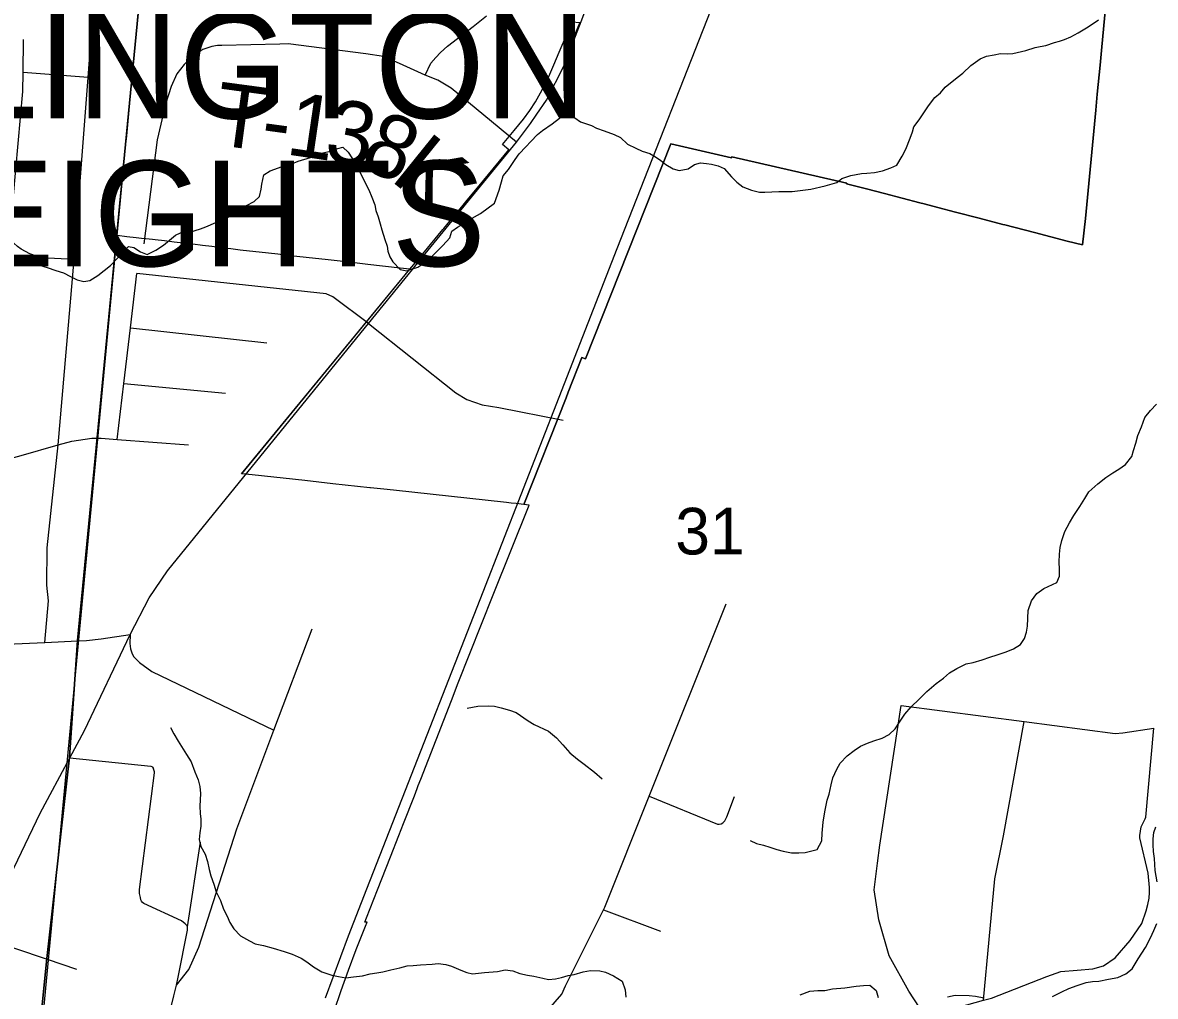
# Model space of a CAD drawing. Extents: x 0 to 34, y -3.9 to 26.2.
# Drawn here: x 2.843 to 3.859, y 17.395 to 18.269 of the extents above; entities that cross this region are included whole.
import ezdxf

# ---------------------------------------------------------------- set-up
doc = ezdxf.new("R2010")
doc.units = 0
for name, color, linetype in [('GM_X_City_Street', 7, 'Continuous'), ('GM_X_Corporation', 7, 'Continuous'), ('GM_X_Corporation_Text', 7, 'Continuous'), ('GM_X_County_Road', 7, 'Continuous'), ('GM_X_Interchange_Ramps', 7, 'Continuous'), ('GM_X_Interstate_Route', 7, 'Continuous'), ('GM_X_Minor_River', 7, 'Continuous'), ('GM_X_Rail_Line', 7, 'Continuous'), ('GM_X_Section', 7, 'Continuous'), ('GM_X_Section_Text', 7, 'Continuous'), ('GM_X_State_Shield', 7, 'Continuous'), ('GM_X_Township_Road', 7, 'Continuous'), ('GM_X_Township_Road_Text', 7, 'Continuous'), ('GM_X_US_Route', 7, 'Continuous')]:
    doc.layers.add(name, color=color, linetype=linetype)

msp = doc.modelspace()

# ---------------------------------------------------------------- linework, layer by layer
at = {"layer": 'GM_X_City_Street'}
for p, q in [((2.9019, 18.2193), (2.8434, 18.2239)), ((2.9397, 17.9947), (3.0621, 17.9811)), ((2.9338, 17.9448), (3.0249, 17.9362)), ((2.9901, 17.6713), (3.0685, 17.6337)), ((2.991, 17.457), (3.0027, 17.533)), ((3.3641, 17.4723), (3.4151, 17.4532))]:
    msp.add_line(p, q, dxfattribs=at)
for points in [[(2.8893, 18.056), (2.8601, 18.0575), (2.8563, 18.0587), (2.8495, 18.0612), (2.8416, 18.0654), (2.8383, 18.0676), (2.8351, 18.0708), (2.8336, 18.0729), (2.8328, 18.0749), (2.8323, 18.0804), (2.8328, 18.0901), (2.8433, 18.2068), (2.8434, 18.2239), (2.8437, 18.2535)], [(2.8629, 17.7123), (2.8661, 17.7496), (2.8646, 17.7637), (2.865, 17.7972), (2.8748, 17.8896), (2.8893, 18.056), (2.9019, 18.2193), (2.9049, 18.2592)], [(2.9278, 17.8946), (2.9338, 17.9448), (2.9397, 17.9947), (2.9455, 18.0435)], [(3.1534, 17.9985), (3.1212, 18.0225), (3.1152, 18.0253), (2.9455, 18.0435)], [(3.1534, 17.9985), (3.2317, 17.9364), (3.2415, 17.9304), (3.2554, 17.9255), (3.2701, 17.9232), (3.3278, 17.9118)], [(2.6306, 17.8842), (2.6867, 17.8819), (2.6993, 17.8814), (2.8142, 17.8768), (2.815, 17.8767), (2.8298, 17.8767), (2.8416, 17.8802), (2.8748, 17.8896), (2.8871, 17.8931), (2.905, 17.8956), (2.9102, 17.8957), (2.9134, 17.8958), (2.9278, 17.8946), (2.9919, 17.8896)], [(3.2531, 17.0012), (3.2564, 17.0369), (3.2762, 17.2484), (3.2789, 17.2779), (3.2811, 17.3213), (3.282, 17.3401), (3.2822, 17.3432), (3.2833, 17.3458), (3.2862, 17.3499), (3.2928, 17.3577), (3.3268, 17.3967), (3.3301, 17.4042), (3.3641, 17.4723), (3.3652, 17.4746), (3.4052, 17.5744), (3.4742, 17.7469)], [(2.981, 17.4048), (2.992, 17.4189), (3.0011, 17.4389), (3.0353, 17.545), (3.0685, 17.6337), (3.1027, 17.7247)], [(2.9396, 17.7194), (2.9392, 17.7114), (2.9399, 17.7065), (2.9412, 17.7021), (2.9429, 17.6994), (2.9479, 17.6942), (2.9588, 17.6864), (2.9901, 17.6713)], [(3.6576, 17.3692), (3.6379, 17.3994), (3.6205, 17.431), (3.6111, 17.4635), (3.6068, 17.4902), (3.61, 17.5142), (3.612, 17.5303), (3.6312, 17.6558)], [(3.6312, 17.6558), (3.7416, 17.6413), (3.8232, 17.6305), (3.83, 17.6311), (3.8578, 17.6353)], [(3.705, 17.3912), (3.7152, 17.5002), (3.723, 17.5387), (3.7416, 17.6413)], [(3.823, 17.4293), (3.8367, 17.4449), (3.8469, 17.4602), (3.851, 17.4715), (3.8524, 17.4771), (3.8535, 17.4828), (3.8538, 17.4878), (3.8538, 17.4923), (3.8526, 17.5052), (3.8451, 17.5369), (3.8453, 17.5392), (3.8465, 17.5468), (3.8501, 17.554), (3.8505, 17.5554), (3.8578, 17.6353)], [(2.8854, 17.6088), (2.9581, 17.6014), (2.959, 17.6009), (2.9596, 17.6004), (2.9604, 17.599)], [(2.991, 17.457), (2.9903, 17.4584), (2.9889, 17.4597), (2.9855, 17.4624), (2.9517, 17.4781), (2.9506, 17.4789), (2.9498, 17.48), (2.9492, 17.4813), (2.9488, 17.4835), (2.948, 17.4871), (2.9478, 17.4907), (2.9613, 17.5953), (2.9612, 17.5962), (2.9604, 17.599)], [(3.4052, 17.5744), (3.4663, 17.5493), (3.4678, 17.5491), (3.4698, 17.5495), (3.4711, 17.5504), (3.473, 17.5523), (3.4746, 17.5559), (3.4815, 17.574)], [(2.981, 17.4048), (2.9827, 17.412), (2.9908, 17.454), (2.9908, 17.4553), (2.991, 17.457)], [(2.8053, 17.4482), (2.865, 17.4281), (2.8913, 17.4192)], [(3.6576, 17.3692), (3.6647, 17.3778), (3.6704, 17.3818), (3.6827, 17.3849), (3.705, 17.3912), (3.7121, 17.3932), (3.7619, 17.4124), (3.7745, 17.417), (3.7889, 17.4181), (3.803, 17.4193), (3.8126, 17.422), (3.823, 17.4293)], [(2.9695, 17.3546), (2.9732, 17.3738), (2.9742, 17.3765), (2.9787, 17.3951), (2.981, 17.4048)]]:
    msp.add_lwpolyline(points, dxfattribs=at)
at = {"layer": 'GM_X_Corporation'}
for points in [[(3.8147, 18.2851), (3.8108, 18.2437), (3.8096, 18.2306), (3.8071, 18.2043), (3.8057, 18.1902), (3.7965, 18.0928), (3.7938, 18.0691), (3.7801, 18.0726), (3.7508, 18.0802), (3.724, 18.0872), (3.7224, 18.0876), (3.7011, 18.0931), (3.6799, 18.0986), (3.6639, 18.1028), (3.6518, 18.1059), (3.648, 18.107), (3.632, 18.1111), (3.6161, 18.1153), (3.6001, 18.1194), (3.5821, 18.1239), (3.5824, 18.1247), (3.4791, 18.1481), (3.479, 18.1473), (3.4246, 18.16), (3.348, 17.9668), (3.3448, 17.968), (3.3325, 17.9371), (3.3305, 17.932), (3.2926, 17.8361), (3.2859, 17.8369), (3.2812, 17.8374), (3.2791, 17.8376), (3.2771, 17.8378), (3.1756, 17.8489), (3.1672, 17.8498), (3.1551, 17.8511), (3.1546, 17.8512), (3.1213, 17.8548), (3.0963, 17.8576), (3.0488, 17.8628), (3.0395, 17.8637), (3.1905, 18.0475), (3.1974, 18.0555), (3.1991, 18.0576), (3.202, 18.0612), (3.2201, 18.083), (3.2204, 18.0833), (3.2208, 18.0839), (3.2248, 18.0887), (3.2369, 18.1033), (3.2407, 18.1079), (3.2567, 18.1272), (3.2792, 18.1545), (3.2734, 18.1593), (3.284, 18.1718), (3.2924, 18.1821), (3.2979, 18.1897), (3.303, 18.1976), (3.3077, 18.2057), (3.3121, 18.2139), (3.3122, 18.2141), (3.3161, 18.2224), (3.3196, 18.2308), (3.3244, 18.242), (3.331, 18.2574), (3.3315, 18.2587), (3.3379, 18.2561), (3.3429, 18.2684), (3.3359, 18.2692)], [(3.1224, 17.3813), (3.1287, 17.3999), (3.1354, 17.4183), (3.1423, 17.4366), (3.1506, 17.4577), (3.152, 17.4612), (3.1501, 17.4614), (3.1516, 17.4652), (3.1614, 17.4903), (3.173, 17.52), (3.1805, 17.539), (3.1846, 17.5497), (3.1945, 17.5748), (3.1969, 17.5811), (3.198, 17.584), (3.2002, 17.5895), (3.2278, 17.6601), (3.2338, 17.6761), (3.265, 17.755), (3.2973, 17.8356), (3.2926, 17.8361), (3.3305, 17.932), (3.3325, 17.9371), (3.3448, 17.968), (3.348, 17.9668), (3.4246, 18.16), (3.479, 18.1473), (3.4791, 18.1481), (3.5824, 18.1247), (3.5821, 18.1239), (3.6001, 18.1194), (3.6161, 18.1153), (3.632, 18.1111), (3.648, 18.107), (3.6518, 18.1059), (3.6639, 18.1028), (3.6799, 18.0986), (3.7011, 18.0931), (3.7224, 18.0876), (3.724, 18.0872), (3.7508, 18.0802), (3.7801, 18.0726), (3.7938, 18.0691), (3.7965, 18.0928), (3.8057, 18.1902), (3.8071, 18.2043), (3.8096, 18.2306), (3.8108, 18.2437), (3.8147, 18.2851)]]:
    msp.add_lwpolyline(points, dxfattribs=at)
at = {"layer": 'GM_X_County_Road'}
msp.add_lwpolyline([(2.5147, 17.6958), (2.5377, 17.697), (2.685, 17.704), (2.6897, 17.7043), (2.8012, 17.7095), (2.8629, 17.7123), (2.8926, 17.7137), (2.9002, 17.7141), (2.9135, 17.7157), (2.9396, 17.7194)], dxfattribs=at)
at = {"layer": 'GM_X_Interchange_Ramps'}
msp.add_lwpolyline([(3.1224, 17.3813), (3.1287, 17.3999), (3.1354, 17.4183), (3.1423, 17.4366), (3.1506, 17.4577), (3.152, 17.4612), (3.1501, 17.4614), (3.1516, 17.4652), (3.1614, 17.4903), (3.173, 17.52), (3.1805, 17.539), (3.1846, 17.5497), (3.1945, 17.5748), (3.1969, 17.5811), (3.198, 17.584), (3.2002, 17.5895), (3.2278, 17.6601), (3.2338, 17.6761), (3.265, 17.755), (3.2973, 17.8356), (3.2926, 17.8361), (3.2859, 17.8369), (3.2812, 17.8374), (3.2791, 17.8376), (3.2771, 17.8378), (3.1756, 17.8489), (3.1672, 17.8498), (3.1551, 17.8511), (3.1546, 17.8512), (3.1213, 17.8548), (3.0963, 17.8576), (3.0488, 17.8628), (3.0397, 17.8637), (3.1905, 18.0475), (3.1818, 18.0484), (3.1528, 18.0516), (3.1359, 18.0535), (3.1251, 18.0547), (3.1144, 18.0559), (3.1059, 18.0569), (3.0974, 18.0578), (3.089, 18.0588), (3.0805, 18.0597), (3.072, 18.0607), (3.0636, 18.0616), (3.0551, 18.0626), (3.0466, 18.0636), (3.0381, 18.0645), (3.0297, 18.0655), (3.0212, 18.0666), (3.0128, 18.0676), (3.0043, 18.0686), (2.9958, 18.0697), (2.9874, 18.0707), (2.9844, 18.0711), (2.9789, 18.0717), (2.9704, 18.0727), (2.962, 18.0736), (2.9595, 18.0739), (2.9535, 18.0746), (2.9496, 18.075), (2.945, 18.0755), (2.9366, 18.0765), (2.9279, 18.0775), (2.9282, 18.0807), (2.9291, 18.0902), (2.93, 18.0996), (2.9309, 18.109), (2.9318, 18.1185), (2.9327, 18.1279), (2.9336, 18.1373), (2.9345, 18.1472), (2.9354, 18.1571), (2.9364, 18.1669), (2.9373, 18.1768), (2.9382, 18.1867), (2.9392, 18.1965), (2.9401, 18.2064), (2.941, 18.2163), (2.942, 18.2261), (2.9429, 18.236), (2.9438, 18.2459), (2.9448, 18.2557), (2.9467, 18.2766)], dxfattribs=at)
at = {"layer": 'GM_X_Interstate_Route'}
for points in [[(2.1, 20.9), (2.1, 17.3946), (2.4456, 17.3795), (2.6087, 17.3724), (2.7655, 17.371), (2.7927, 17.3686), (2.8236, 17.3675), (2.8585, 17.366), (2.8647, 17.4286), (2.8852, 17.6093), (2.8923, 17.7142), (2.91, 17.8963), (2.9486, 18.2958)], [(2.9486, 18.2958), (2.91, 17.8963), (2.8923, 17.7142), (2.8852, 17.6093), (2.8647, 17.4286), (2.8585, 17.366), (2.8849, 17.3636), (2.9693, 17.3552), (3.0981, 17.3414), (3.1746, 17.3332), (3.2809, 17.3219), (3.3735, 17.3129), (3.4727, 17.3022), (3.6509, 17.2827), (3.7275, 17.2753), (4.0006, 17.2468), (4.2279, 17.2278), (4.5375, 17.2019), (4.6914, 17.1875), (4.8481, 17.1727)]]:
    msp.add_lwpolyline(points, dxfattribs=at)
at = {"layer": 'GM_X_Minor_River'}
for points in [[(3.1929, 18.0477), (3.1975, 18.0491), (3.2057, 18.0544), (3.2108, 18.0592), (3.2199, 18.0687), (3.2263, 18.0756), (3.228, 18.0816), (3.2331, 18.0852), (3.2385, 18.088), (3.2436, 18.0916), (3.2537, 18.0973), (3.2662, 18.1067), (3.2705, 18.1183), (3.2727, 18.1258), (3.274, 18.131), (3.2788, 18.1369), (3.2849, 18.1458), (3.2885, 18.151), (3.2944, 18.1572), (3.2988, 18.1619), (3.3048, 18.1682), (3.3095, 18.1718), (3.3181, 18.1779), (3.3247, 18.1829), (3.3305, 18.1853), (3.3384, 18.1831), (3.3436, 18.1795), (3.3533, 18.1764), (3.3578, 18.1739), (3.3646, 18.1714), (3.3736, 18.1683), (3.3795, 18.1654), (3.3857, 18.1595), (3.3932, 18.1561), (3.3988, 18.1532), (3.4056, 18.1511), (3.4108, 18.1482), (3.4156, 18.1449), (3.42, 18.1413), (3.4267, 18.1373), (3.4319, 18.1359), (3.44, 18.1375), (3.4458, 18.1414), (3.4512, 18.1427), (3.4565, 18.1421), (3.461, 18.1415), (3.4671, 18.1401), (3.4723, 18.1376), (3.4788, 18.1302), (3.4836, 18.1254), (3.4891, 18.1214), (3.497, 18.1184), (3.5041, 18.1166), (3.5087, 18.1164), (3.5213, 18.117), (3.5334, 18.1172), (3.5502, 18.1192), (3.5629, 18.1221), (3.5733, 18.1251), (3.578, 18.1287), (3.5861, 18.1314), (3.5956, 18.1333), (3.6002, 18.1335), (3.6071, 18.134), (3.6143, 18.1356), (3.622, 18.1383), (3.6271, 18.1407), (3.632, 18.1489), (3.6353, 18.1552), (3.6391, 18.1649), (3.6412, 18.1706), (3.6425, 18.1751), (3.6473, 18.1813), (3.6526, 18.1895), (3.6558, 18.1939), (3.6614, 18.2013), (3.6665, 18.2056), (3.6705, 18.2108), (3.6815, 18.2194), (3.6866, 18.2234), (3.6937, 18.2303), (3.7019, 18.2361), (3.7077, 18.2385), (3.7146, 18.2397), (3.7203, 18.241), (3.7268, 18.2407), (3.7314, 18.2409), (3.7429, 18.2435), (3.7513, 18.2462), (3.7559, 18.2471), (3.7609, 18.2481), (3.7686, 18.2508), (3.7732, 18.2521), (3.7778, 18.2535), (3.7832, 18.2559), (3.7898, 18.2594), (3.7988, 18.2648), (3.8082, 18.2712)], [(2.8336, 18.0546), (2.8457, 18.0534), (2.8521, 18.052), (2.8582, 18.051), (2.8649, 18.0488), (2.8728, 18.0462), (2.8796, 18.044), (2.8859, 18.0407), (2.8919, 18.0378), (2.8979, 18.0364), (2.9032, 18.0373), (2.9106, 18.0416), (2.922, 18.0506), (2.9331, 18.0627), (2.9379, 18.0678), (2.9428, 18.0668), (2.9487, 18.0628), (2.9547, 18.0606), (2.9625, 18.0645), (2.9695, 18.0688), (2.9801, 18.0778), (2.9847, 18.0799), (2.9931, 18.0807), (3.0027, 18.0837), (3.0074, 18.0855), (3.0163, 18.0893), (3.0228, 18.0913), (3.0302, 18.0959), (3.0369, 18.1013), (3.0438, 18.1045), (3.0508, 18.108), (3.0556, 18.1127), (3.057, 18.1191), (3.0575, 18.1237), (3.0594, 18.1319), (3.0652, 18.1355), (3.0725, 18.1382), (3.0783, 18.1403), (3.0845, 18.1419), (3.0903, 18.1444), (3.1014, 18.1477), (3.1107, 18.1515), (3.118, 18.1531), (3.1257, 18.1558), (3.1303, 18.1568), (3.135, 18.1524), (3.1383, 18.1473), (3.1426, 18.141), (3.1454, 18.1348), (3.1503, 18.1248), (3.1535, 18.1185), (3.1562, 18.112), (3.159, 18.105), (3.16, 18.1), (3.162, 18.0942), (3.1637, 18.0881), (3.1653, 18.0827), (3.168, 18.0739), (3.1701, 18.0681), (3.1707, 18.0635), (3.1724, 18.0585), (3.1752, 18.0538), (3.1818, 18.0471), (3.1878, 18.046), (3.1929, 18.0477)], [(3.4957, 17.5347), (3.5013, 17.5318), (3.5077, 17.5304), (3.5133, 17.5286), (3.5197, 17.5264), (3.5253, 17.5251), (3.5329, 17.5236), (3.5393, 17.5234), (3.545, 17.5239), (3.5558, 17.5265), (3.5599, 17.5343), (3.5602, 17.5411), (3.5613, 17.5509), (3.5628, 17.5604), (3.5648, 17.5709), (3.5665, 17.5762), (3.5683, 17.5845), (3.5697, 17.5909), (3.5735, 17.5987), (3.5763, 17.6039), (3.5827, 17.6105), (3.5889, 17.6155), (3.5948, 17.6191), (3.601, 17.6219), (3.6067, 17.6239), (3.6141, 17.6263), (3.6203, 17.6298), (3.6258, 17.6349), (3.6295, 17.6409), (3.6343, 17.6479), (3.6402, 17.6545), (3.6474, 17.6614), (3.6541, 17.6683), (3.6624, 17.6756), (3.669, 17.6803), (3.6745, 17.685), (3.6811, 17.6889), (3.6893, 17.6931), (3.6958, 17.6943), (3.7039, 17.6967), (3.7108, 17.699), (3.7173, 17.7011), (3.7254, 17.7038), (3.732, 17.7065), (3.7382, 17.7105), (3.7419, 17.716), (3.7436, 17.7216), (3.7446, 17.7269), (3.7451, 17.7409), (3.7481, 17.7496), (3.7529, 17.7562), (3.7592, 17.7609), (3.7708, 17.7661), (3.7733, 17.7717), (3.7732, 17.7782), (3.773, 17.7843), (3.7733, 17.7915), (3.7739, 17.7975), (3.7753, 17.8039), (3.7779, 17.8118), (3.782, 17.8196), (3.7861, 17.8263), (3.7914, 17.8344), (3.7958, 17.8415), (3.7995, 17.8474), (3.8077, 17.8547), (3.8148, 17.8604), (3.821, 17.8647), (3.8265, 17.8679), (3.8323, 17.8719), (3.838, 17.8792), (3.8397, 17.8845), (3.8415, 17.8913), (3.8433, 17.898), (3.8466, 17.9059), (3.8496, 17.9141), (3.8548, 17.9204), (3.8603, 17.9262)], [(3.2419, 17.6535), (3.2515, 17.655), (3.2606, 17.6554), (3.2663, 17.6551), (3.2724, 17.6537), (3.2799, 17.6515), (3.2859, 17.6494), (3.2966, 17.6421), (3.3018, 17.6388), (3.3149, 17.6326), (3.3218, 17.6266), (3.3277, 17.6203), (3.3338, 17.6132), (3.3408, 17.6076), (3.3468, 17.6032), (3.356, 17.5959), (3.363, 17.5899)], [(2.9756, 17.636), (2.9788, 17.6302), (2.9827, 17.6236), (2.9899, 17.6119), (2.9942, 17.6052), (2.9976, 17.5963), (3.0004, 17.589), (3.002, 17.5829), (3.0026, 17.5768), (3.0021, 17.5654), (3.0022, 17.5589), (3.0028, 17.5536), (3.0029, 17.5475), (3.0019, 17.5414), (3.0013, 17.5354), (3.003, 17.5292), (3.0069, 17.5222), (3.0089, 17.5157), (3.0105, 17.5084), (3.0118, 17.503), (3.0146, 17.4953), (3.0166, 17.4884), (3.0204, 17.4806), (3.0232, 17.4729), (3.0264, 17.4667), (3.0288, 17.4609), (3.0324, 17.4554), (3.0386, 17.4491), (3.0464, 17.4446), (3.0516, 17.4417), (3.0591, 17.4403), (3.0678, 17.438), (3.0775, 17.4349), (3.0847, 17.4327), (3.0929, 17.429), (3.0981, 17.4257), (3.104, 17.4213), (3.1114, 17.4168), (3.1204, 17.4138), (3.1264, 17.4124), (3.1329, 17.4114), (3.1397, 17.4122), (3.1478, 17.413), (3.1547, 17.415), (3.1608, 17.4159), (3.1661, 17.4168), (3.1734, 17.4184), (3.1815, 17.4204), (3.188, 17.422), (3.1933, 17.4225), (3.1998, 17.423), (3.2105, 17.4237), (3.2158, 17.4243), (3.2226, 17.4232), (3.2279, 17.4219), (3.2361, 17.4181), (3.2414, 17.416), (3.2466, 17.415), (3.2573, 17.4161), (3.2691, 17.4171), (3.276, 17.4184), (3.2828, 17.4177), (3.2892, 17.4152), (3.296, 17.4137), (3.3016, 17.4127), (3.3096, 17.4109), (3.3148, 17.4099), (3.3209, 17.4104), (3.3263, 17.4117), (3.3325, 17.4134), (3.3378, 17.4143), (3.3459, 17.4166), (3.3524, 17.4179), (3.3607, 17.4175), (3.366, 17.4165), (3.3731, 17.4132), (3.3809, 17.4083), (3.3836, 17.4006), (3.3841, 17.3941)], [(3.8609, 17.4975), (3.8591, 17.5078), (3.8584, 17.5185), (3.8575, 17.5246), (3.8573, 17.5307), (3.8571, 17.536), (3.8577, 17.5417), (3.8595, 17.5469)], [(3.7668, 17.3946), (3.7754, 17.3988), (3.7816, 17.4016), (3.7889, 17.4043), (3.797, 17.407), (3.8027, 17.4079), (3.8084, 17.4084), (3.8172, 17.41), (3.8256, 17.4115), (3.8326, 17.415), (3.8385, 17.4194), (3.8438, 17.4283), (3.8503, 17.4386), (3.8548, 17.4472), (3.8577, 17.4539), (3.8606, 17.4602)], [(3.5404, 17.396), (3.5493, 17.3994), (3.5565, 17.3999), (3.5626, 17.4), (3.5695, 17.4013), (3.5806, 17.4023), (3.5909, 17.4038), (3.5974, 17.4043), (3.6031, 17.4048), (3.6086, 17.4), (3.6106, 17.3938)], [(3.6726, 17.3943), (3.6795, 17.3959), (3.692, 17.3954), (3.6977, 17.3948), (3.7056, 17.3933)]]:
    msp.add_lwpolyline(points, dxfattribs=at)
at = {"layer": 'GM_X_Rail_Line'}
msp.add_lwpolyline([(3.1147, 17.3933), (3.1353, 17.4491), (3.1518, 17.4911), (3.1752, 17.5507), (3.2561, 17.7578), (3.3244, 17.9326), (3.3765, 18.0659), (3.4712, 18.3073)], dxfattribs=at)
at = {"layer": 'GM_X_Section'}
msp.add_lwpolyline([(2.9569, 18.3849), (3.9744, 18.2676), (3.8804, 17.2579), (2.8603, 17.3639)], close=True, dxfattribs=at)
at = {"layer": 'GM_X_State_Shield'}
msp.add_lwpolyline([(2.1, 18.4182), (2.1, 17.392), (2.8603, 17.3639), (2.9569, 18.3849)], close=True, dxfattribs=at)
at = {"layer": 'GM_X_Township_Road'}
for points in [[(3.2042, 18.2216), (3.2093, 18.2323), (3.2138, 18.2374), (3.2179, 18.2419), (3.2242, 18.2475), (3.2471, 18.2651), (3.2591, 18.2747)], [(3.0739, 18.2493), (3.0218, 18.2482), (3.0178, 18.248), (3.0128, 18.2472), (3.0048, 18.2444), (2.9994, 18.241), (2.9914, 18.2348), (2.988, 18.2312), (2.9815, 18.2227), (2.9763, 18.2114), (2.9711, 18.1956), (2.9636, 18.1634), (2.9519, 18.0702)], [(3.2861, 18.1615), (3.2274, 18.2099), (3.2156, 18.2169), (3.2042, 18.2216), (3.181, 18.2321), (3.1669, 18.2381), (3.151, 18.2407), (3.0811, 18.2495), (3.0739, 18.2493)]]:
    msp.add_lwpolyline(points, dxfattribs=at)
at = {"layer": 'GM_X_US_Route'}
for points in [[(3.3043, 18.1864), (3.3129, 18.199), (3.3289, 18.2302), (3.3389, 18.2564), (3.344, 18.2697), (3.3492, 18.2831)], [(3.1929, 18.0472), (3.1962, 18.0513), (3.2861, 18.1615), (3.2986, 18.178), (3.3043, 18.1864)], [(3.0454, 17.8657), (3.1534, 17.9985), (3.1929, 18.0472)], [(2.6512, 17.1227), (2.6901, 17.2031), (2.7325, 17.2907), (2.747, 17.324), (2.7658, 17.3705), (2.8053, 17.4482), (2.8093, 17.4563), (2.8149, 17.468), (2.8587, 17.5592), (2.8854, 17.6088), (2.8986, 17.6334), (2.9396, 17.7194), (2.9564, 17.7524), (2.973, 17.7766), (3.0454, 17.8657)]]:
    msp.add_lwpolyline(points, dxfattribs=at)

# ---------------------------------------------------------------- texts
at = {"layer": 'GM_X_Corporation_Text'}
for s, p in [('ARLINGTON', (2.6102, 18.1826)), ('HEIGHTS', (2.6956, 18.05))]:
    msp.add_text(s, height=0.0947, rotation=0, dxfattribs=at).set_placement(p)
at = {"layer": 'GM_X_Section_Text'}
msp.add_text('31', height=0.04186, rotation=0, dxfattribs=at).set_placement((3.4285, 17.7913))
at = {"layer": 'GM_X_Township_Road_Text'}
for s, rotation, p in [('T', 352.3402, (3.013, 18.1594)), ('1', 351.6705, (3.078, 18.1506)), ('3', 349.3381, (3.1121, 18.1456)), ('-', 352.2093, (3.0551, 18.1537)), ('8', 335.9049, (3.1431, 18.1402)), ('K', 321.1331, (3.1718, 18.1279))]:
    msp.add_text(s, height=0.0568, rotation=rotation, dxfattribs=at).set_placement(p)

doc.saveas('drawing.dxf')
